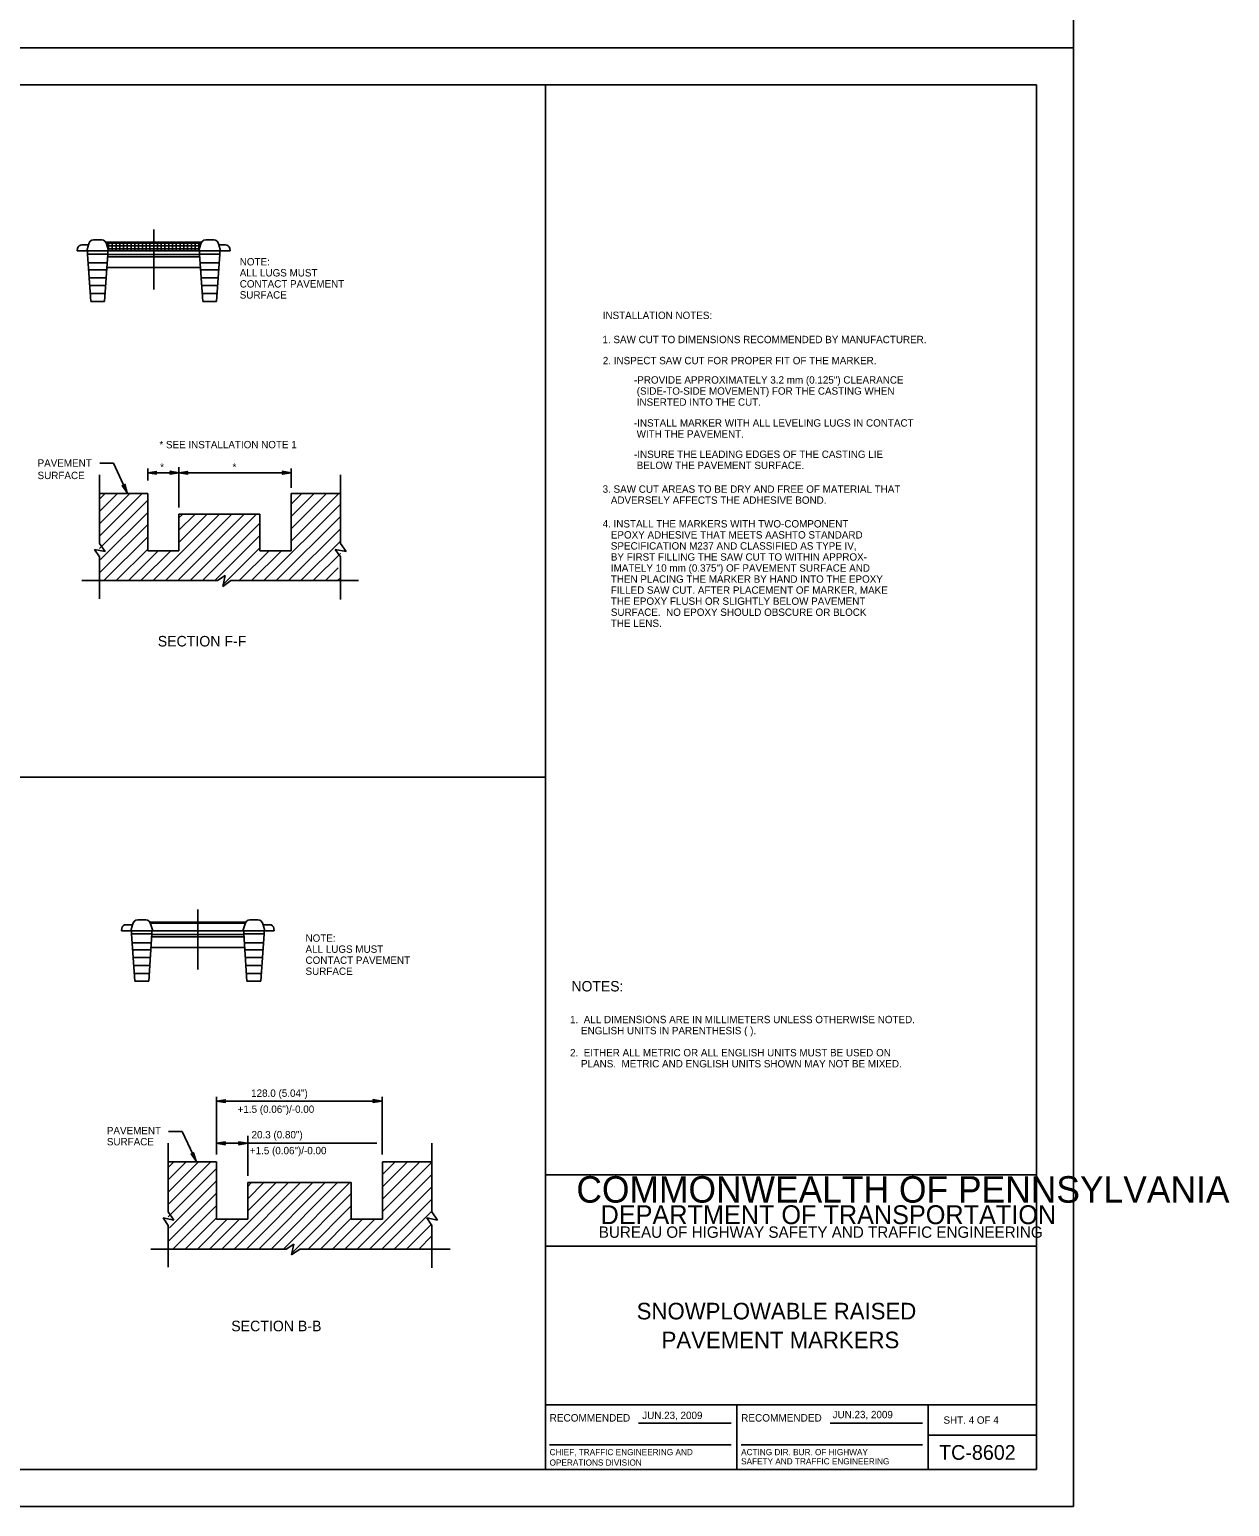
# Model space of a CAD drawing. Extents: x 639362 to 641108, y 298458 to 299646.
# Drawn here: x 640619 to 641108, y 298458 to 299059 of the extents above; entities that cross this region are included whole.
import ezdxf

# ---------------------------------------------------------------- set-up
doc = ezdxf.new("R2010")
doc.units = 0
for name, color, linetype in [('1', 7, 'Continuous'), ('2', 7, 'Continuous'), ('PLT-BNDY', 7, 'Continuous')]:
    doc.layers.add(name, color=color, linetype=linetype)

msp = doc.modelspace()

# ---------------------------------------------------------------- linework, layer by layer
at = {"layer": '1'}
for p, q in [((640243.31, 299036.63), (641029.31, 299036.63)), ((640829.31, 298592.63), (640829.31, 299036.63)), ((641029.31, 298472.63), (641029.31, 299036.63)), ((640243.31, 298754.63), (640829.31, 298754.63)), ((640829.31, 298472.63), (640829.31, 298592.63)), ((640829.31, 298592.63), (641029.31, 298592.63)), ((641029.31, 298563.63), (640829.31, 298563.63)), ((640829.31, 298499), (641029.31, 298499)), ((640907.31, 298499), (640907.31, 298472.63)), ((640985.19, 298472.63), (640985.19, 298499)), ((640867.24, 298491.57), (640904.87, 298491.57)), ((640945.24, 298491.57), (640982.87, 298491.57)), ((640830.99, 298482.68), (640904.87, 298482.68)), ((640908.99, 298482.68), (640982.87, 298482.68)), ((640985.19, 298486.63), (641029.31, 298486.63)), ((641029.31, 298472.63), (640243.31, 298472.63)), ((640243.31, 298472.63), (640829.31, 298472.63))]:
    msp.add_line(p, q, dxfattribs=at)
at = {"layer": '2'}
for p, q in [((640669.77, 298977.68), (640669.77, 298953.22)), ((640638.64, 298969.01), (640638.78, 298969.98)), ((640643.2, 298971.48), (640640.53, 298971.48)), ((640642.5, 298969.01), (640643.19, 298971.43)), ((640645.29, 298973.5), (640648.59, 298973.5)), ((640650.27, 298972.5), (640689.27, 298972.5)), ((640650.48, 298972.11), (640689.08, 298972.11)), ((640651.38, 298969.01), (640650.68, 298971.43)), ((640651.07, 298971.07), (640688.46, 298971.07)), ((640651.07, 298969.88), (640688.46, 298969.88)), ((640651.36, 298972.11), (640651.36, 298969.01)), ((640652.9, 298972.11), (640652.9, 298969.01)), ((640654.43, 298972.11), (640654.43, 298969.01)), ((640655.96, 298972.11), (640655.96, 298969.01)), ((640657.5, 298972.11), (640657.5, 298969.01)), ((640659.03, 298972.11), (640659.03, 298969.01)), ((640660.56, 298972.11), (640660.56, 298969.01)), ((640662.1, 298972.11), (640662.1, 298969.01)), ((640663.63, 298972.11), (640663.63, 298969.01)), ((640665.17, 298972.11), (640665.17, 298969.01)), ((640666.7, 298972.11), (640666.7, 298969.01)), ((640668.23, 298972.11), (640668.23, 298969.01)), ((640669.77, 298972.11), (640669.77, 298969.01)), ((640671.3, 298972.11), (640671.3, 298969.01)), ((640672.83, 298972.11), (640672.83, 298969.01)), ((640674.36, 298972.11), (640674.36, 298969.01)), ((640675.9, 298972.11), (640675.9, 298969.01)), ((640677.43, 298972.11), (640677.43, 298969.01)), ((640678.97, 298972.11), (640678.97, 298969.01)), ((640680.5, 298972.11), (640680.5, 298969.01)), ((640682.03, 298972.11), (640682.03, 298969.01)), ((640683.57, 298972.11), (640683.57, 298969.01)), ((640685.1, 298972.11), (640685.1, 298969.01)), ((640686.63, 298972.11), (640686.63, 298969.01)), ((640688.15, 298969.01), (640688.85, 298971.43)), ((640688.17, 298972.11), (640688.17, 298969.01)), ((640694.24, 298973.5), (640690.94, 298973.5)), ((640696.33, 298971.48), (640699, 298971.48)), ((640697.03, 298969.01), (640696.33, 298971.43)), ((640700.89, 298969.01), (640700.75, 298969.98)), ((640642.75, 298969.01), (640638.64, 298969.01)), ((640642.5, 298969.01), (640651.38, 298969.01)), ((640642.79, 298967.68), (640642.79, 298969.01)), ((640644.12, 298948.4), (640642.79, 298967.68)), ((640642.79, 298967.68), (640651.09, 298967.68)), ((640650.84, 298964.12), (640643.03, 298964.12)), ((640649.77, 298948.4), (640651.09, 298967.68)), ((640651.01, 298966.54), (640688.52, 298966.54)), ((640651.07, 298967.46), (640688.46, 298967.46)), ((640651.09, 298967.68), (640651.09, 298969.01)), ((640651.13, 298969.01), (640688.4, 298969.01)), ((640688.15, 298969.01), (640697.03, 298969.01)), ((640688.44, 298967.68), (640688.44, 298969.01)), ((640689.77, 298948.4), (640688.44, 298967.68)), ((640688.44, 298967.68), (640696.74, 298967.68)), ((640688.68, 298964.12), (640696.5, 298964.12)), ((640695.41, 298948.4), (640696.74, 298967.68)), ((640696.74, 298967.68), (640696.74, 298969.01)), ((640696.78, 298969.01), (640700.89, 298969.01)), ((640650.65, 298961.26), (640643.23, 298961.26)), ((640650.43, 298958.05), (640643.45, 298958.05)), ((640650.71, 298962.2), (640688.82, 298962.2)), ((640688.88, 298961.26), (640696.3, 298961.26)), ((640689.1, 298958.05), (640696.08, 298958.05)), ((640650.21, 298954.83), (640643.68, 298954.83)), ((640649.99, 298951.62), (640643.9, 298951.62)), ((640689.32, 298954.83), (640695.85, 298954.83)), ((640689.54, 298951.62), (640695.63, 298951.62)), ((640649.77, 298948.4), (640644.12, 298948.4)), ((640689.77, 298948.4), (640695.41, 298948.4)), ((640647.82, 298882.56), (640653.38, 298882.56)), ((640653.38, 298882.56), (640659, 298870.44)), ((640667.32, 298880.4), (640667.32, 298875.51)), ((640680.07, 298880.95), (640680.07, 298864.44)), ((640725.71, 298880.4), (640725.71, 298872.49)), ((640647.65, 298877.84), (640647.65, 298849.8)), ((640667.32, 298878.62), (640725.71, 298878.62)), ((640745.78, 298877.84), (640745.78, 298849.8)), ((640667.32, 298870.23), (640647.65, 298870.23)), ((640647.65, 298867.87), (640650.01, 298870.23)), ((640647.65, 298862.86), (640655.02, 298870.23)), ((640647.65, 298857.85), (640660.03, 298870.23)), ((640647.65, 298852.84), (640665.04, 298870.23)), ((640647.65, 298847.83), (640667.32, 298867.5)), ((640667.32, 298870.23), (640667.32, 298846.76)), ((640725.71, 298870.23), (640725.71, 298846.86)), ((640725.71, 298870.23), (640745.78, 298870.23)), ((640725.71, 298865.79), (640730.15, 298870.23)), ((640725.71, 298860.78), (640735.16, 298870.23)), ((640725.71, 298855.77), (640740.17, 298870.23)), ((640725.71, 298850.77), (640745.18, 298870.23)), ((640648.15, 298843.33), (640667.32, 298862.49)), ((640669.56, 298834.68), (640696.61, 298861.73)), ((640674.56, 298834.68), (640701.62, 298861.73)), ((640679.57, 298834.68), (640706.63, 298861.73)), ((640680.07, 298861.73), (640680.07, 298846.86)), ((640712.96, 298861.73), (640680.07, 298861.73)), ((640680.07, 298860.22), (640681.58, 298861.73)), ((640680.07, 298855.21), (640686.59, 298861.73)), ((640680.07, 298850.2), (640691.6, 298861.73)), ((640684.58, 298834.68), (640711.63, 298861.73)), ((640712.96, 298861.73), (640712.96, 298846.76)), ((640714.63, 298834.68), (640745.78, 298865.82)), ((640647.65, 298837.81), (640667.32, 298857.48)), ((640689.59, 298834.68), (640712.96, 298858.05)), ((640719.64, 298834.68), (640745.78, 298860.81)), ((640724.65, 298834.68), (640745.78, 298855.81)), ((640650, 298846.51), (640647.65, 298849.8)), ((640649.52, 298834.68), (640667.32, 298852.47)), ((640694.6, 298834.68), (640712.96, 298853.04)), ((640729.66, 298834.68), (640745.78, 298850.8)), ((640748.13, 298846.51), (640745.78, 298849.8)), ((640647.65, 298844.33), (640645.6, 298847.41)), ((640645.6, 298847.41), (640650, 298846.51)), ((640647.65, 298844.33), (640647.65, 298827.29)), ((640654.53, 298834.68), (640667.32, 298847.47)), ((640659.54, 298834.68), (640671.65, 298846.79)), ((640664.55, 298834.68), (640676.7, 298846.83)), ((640667.32, 298846.86), (640680.07, 298846.86)), ((640698.1, 298833.17), (640712.96, 298848.03)), ((640704.62, 298834.68), (640716.8, 298846.86)), ((640709.62, 298834.68), (640721.8, 298846.86)), ((640712.96, 298846.86), (640725.71, 298846.86)), ((640734.67, 298834.68), (640745.78, 298845.79)), ((640745.78, 298844.33), (640743.73, 298847.41)), ((640743.73, 298847.41), (640748.13, 298846.51)), ((640745.78, 298844.33), (640745.78, 298827.06)), ((640739.68, 298834.68), (640744.9, 298839.89)), ((640695.75, 298834.68), (640640.55, 298834.68)), ((640695.75, 298834.68), (640698.83, 298836.73)), ((640698.83, 298836.73), (640697.93, 298832.33)), ((640697.93, 298832.33), (640701.22, 298834.68)), ((640753.23, 298834.68), (640701.22, 298834.68)), ((640744.68, 298834.68), (640745.78, 298835.77)), ((640687.74, 298700.77), (640687.74, 298676.31)), ((640656.61, 298692.1), (640656.76, 298693.07)), ((640661.18, 298694.57), (640658.51, 298694.57)), ((640660.47, 298692.1), (640661.17, 298694.53)), ((640663.27, 298696.59), (640666.56, 298696.59)), ((640668.24, 298695.6), (640707.24, 298695.6)), ((640668.46, 298695.2), (640707.06, 298695.2)), ((640669.35, 298692.1), (640668.66, 298694.53)), ((640706.13, 298692.1), (640706.82, 298694.53)), ((640712.21, 298696.59), (640708.92, 298696.59)), ((640714.3, 298694.57), (640716.97, 298694.57)), ((640715, 298692.1), (640714.31, 298694.53)), ((640718.87, 298692.1), (640718.72, 298693.07)), ((640660.72, 298692.1), (640656.61, 298692.1)), ((640660.47, 298692.1), (640669.35, 298692.1)), ((640660.76, 298690.78), (640660.76, 298692.1)), ((640662.09, 298671.5), (640660.76, 298690.78)), ((640660.76, 298690.78), (640669.06, 298690.78)), ((640668.82, 298687.21), (640661.01, 298687.21)), ((640667.74, 298671.5), (640669.06, 298690.78)), ((640668.98, 298689.63), (640706.49, 298689.63)), ((640669.05, 298690.55), (640706.43, 298690.55)), ((640669.06, 298690.78), (640669.06, 298692.1)), ((640669.1, 298692.1), (640706.37, 298692.1)), ((640706.13, 298692.1), (640715, 298692.1)), ((640706.41, 298690.78), (640706.41, 298692.1)), ((640707.74, 298671.5), (640706.41, 298690.78)), ((640706.41, 298690.78), (640714.72, 298690.78)), ((640706.66, 298687.21), (640714.47, 298687.21)), ((640713.38, 298671.5), (640714.72, 298690.78)), ((640714.72, 298690.78), (640714.72, 298692.1)), ((640714.76, 298692.1), (640718.87, 298692.1)), ((640668.62, 298684.35), (640661.2, 298684.35)), ((640668.4, 298681.14), (640661.43, 298681.14)), ((640668.69, 298685.3), (640706.79, 298685.3)), ((640706.85, 298684.35), (640714.27, 298684.35)), ((640707.08, 298681.14), (640714.05, 298681.14)), ((640668.18, 298677.93), (640661.65, 298677.93)), ((640707.3, 298677.93), (640713.83, 298677.93)), ((640667.96, 298674.71), (640661.87, 298674.71)), ((640667.74, 298671.5), (640662.09, 298671.5)), ((640707.52, 298674.71), (640713.6, 298674.71)), ((640707.74, 298671.5), (640713.38, 298671.5)), ((640695.32, 298624.5), (640695.32, 298601)), ((640695.32, 298622.72), (640762.65, 298622.72)), ((640762.82, 298624.5), (640762.82, 298601)), ((640675.82, 298610.34), (640681.38, 298610.34)), ((640681.38, 298610.34), (640687.01, 298598.21)), ((640675.65, 298605.61), (640675.65, 298577.57)), ((640695.32, 298605.54), (640760.58, 298605.54)), ((640708.07, 298608.54), (640708.07, 298592.22)), ((640783.03, 298605.61), (640783.03, 298577.57)), ((640695.32, 298598), (640675.65, 298598)), ((640675.65, 298595.64), (640678.02, 298598)), ((640675.65, 298590.63), (640683.03, 298598)), ((640675.65, 298585.62), (640688.04, 298598)), ((640675.65, 298580.61), (640693.04, 298598)), ((640695.32, 298598), (640695.32, 298574.53)), ((640762.96, 298598), (640762.96, 298574.63)), ((640762.96, 298598), (640783.03, 298598)), ((640762.96, 298582.78), (640778.19, 298598)), ((640762.96, 298587.78), (640773.18, 298598)), ((640762.96, 298592.79), (640768.17, 298598)), ((640762.96, 298577.77), (640783.03, 298597.84)), ((640675.65, 298575.6), (640695.32, 298595.27)), ((640752.65, 298562.45), (640783.03, 298592.83)), ((640675.65, 298565.59), (640695.32, 298585.26)), ((640676.16, 298571.1), (640695.32, 298590.27)), ((640697.56, 298562.45), (640724.61, 298589.5)), ((640702.57, 298562.45), (640729.62, 298589.5)), ((640707.58, 298562.45), (640734.63, 298589.5)), ((640708.07, 298589.5), (640708.07, 298574.63)), ((640750.21, 298589.5), (640708.07, 298589.5)), ((640708.07, 298587.99), (640709.59, 298589.5)), ((640708.07, 298582.98), (640714.6, 298589.5)), ((640708.07, 298577.97), (640719.6, 298589.5)), ((640712.59, 298562.45), (640739.64, 298589.5)), ((640717.59, 298562.45), (640744.65, 298589.5)), ((640722.6, 298562.45), (640749.66, 298589.5)), ((640726.11, 298560.95), (640750.21, 298585.05)), ((640750.21, 298589.5), (640750.21, 298574.53)), ((640757.66, 298562.45), (640783.03, 298587.82)), ((640677.53, 298562.45), (640695.32, 298580.25)), ((640732.62, 298562.45), (640750.21, 298580.04)), ((640762.67, 298562.45), (640783.03, 298582.81)), ((640675.65, 298572.11), (640673.6, 298575.19)), ((640673.6, 298575.19), (640678, 298574.28)), ((640678, 298574.28), (640675.65, 298577.57)), ((640682.53, 298562.45), (640695.32, 298575.24)), ((640687.54, 298562.45), (640699.66, 298574.57)), ((640692.55, 298562.45), (640704.7, 298574.6)), ((640695.32, 298574.63), (640708.07, 298574.63)), ((640737.63, 298562.45), (640750.21, 298575.03)), ((640742.64, 298562.45), (640754.82, 298574.63)), ((640747.64, 298562.45), (640759.82, 298574.63)), ((640750.21, 298574.63), (640762.96, 298574.63)), ((640767.68, 298562.45), (640782.93, 298577.71)), ((640783.03, 298572.11), (640780.98, 298575.19)), ((640780.98, 298575.19), (640785.38, 298574.28)), ((640785.38, 298574.28), (640783.03, 298577.57)), ((640675.65, 298572.11), (640675.65, 298555.07)), ((640772.69, 298562.45), (640782.75, 298572.52)), ((640777.7, 298562.45), (640783.03, 298567.78)), ((640783.03, 298572.11), (640783.03, 298554.84)), ((640723.76, 298562.45), (640668.55, 298562.45)), ((640723.76, 298562.45), (640726.84, 298564.5)), ((640726.84, 298564.5), (640725.93, 298560.1)), ((640725.93, 298560.1), (640729.22, 298562.45)), ((640790.48, 298562.45), (640729.22, 298562.45))]:
    msp.add_line(p, q, dxfattribs=at)
for points in [[(640657.96, 298873.71), (640657.79, 298873.49), (640659, 298870.44), (640657.96, 298873.71), (640658.02, 298873.93), (640659, 298870.44), (640657.48, 298873.34), (640657.21, 298873.35), (640659, 298870.44), (640656.98, 298873.45), (640657.21, 298873.35)], [(640670.72, 298878.2), (640670.6, 298878.44), (640667.32, 298878.62), (640670.72, 298878.2), (640670.9, 298878.05), (640667.32, 298878.62), (640670.59, 298878.79), (640670.71, 298879.03), (640667.32, 298878.62), (640670.9, 298879.19), (640670.71, 298879.03)], [(640676.59, 298879.05), (640676.71, 298878.8), (640679.99, 298878.62), (640676.59, 298879.05), (640676.42, 298879.2), (640679.99, 298878.62), (640676.72, 298878.46), (640676.6, 298878.22), (640679.99, 298878.62), (640676.42, 298878.05), (640676.6, 298878.22)], [(640683.47, 298878.2), (640683.35, 298878.44), (640680.07, 298878.62), (640683.47, 298878.2), (640683.65, 298878.04), (640680.07, 298878.62), (640683.34, 298878.79), (640683.46, 298879.03), (640680.07, 298878.62), (640683.65, 298879.19), (640683.46, 298879.03)], [(640722.31, 298879.05), (640722.43, 298878.8), (640725.71, 298878.62), (640722.31, 298879.05), (640722.13, 298879.2), (640725.71, 298878.62), (640722.44, 298878.46), (640722.32, 298878.22), (640725.71, 298878.62), (640722.13, 298878.05), (640722.32, 298878.22)], [(640698.73, 298622.3), (640698.6, 298622.54), (640695.32, 298622.72), (640698.73, 298622.3), (640698.9, 298622.15), (640695.32, 298622.72), (640698.6, 298622.89), (640698.72, 298623.13), (640695.32, 298622.72), (640698.9, 298623.29), (640698.72, 298623.13)], [(640759.25, 298623.15), (640759.38, 298622.9), (640762.65, 298622.72), (640759.25, 298623.15), (640759.08, 298623.3), (640762.65, 298622.72), (640759.38, 298622.56), (640759.26, 298622.32), (640762.65, 298622.72), (640759.08, 298622.15), (640759.26, 298622.32)], [(640698.73, 298605.11), (640698.6, 298605.36), (640695.32, 298605.54), (640698.73, 298605.11), (640698.9, 298604.96), (640695.32, 298605.54), (640698.6, 298605.7), (640698.72, 298605.94), (640695.32, 298605.54), (640698.9, 298606.11), (640698.72, 298605.94)], [(640704.59, 298605.96), (640704.72, 298605.72), (640708, 298605.53), (640704.59, 298605.96), (640704.42, 298606.11), (640708, 298605.53), (640704.73, 298605.37), (640704.6, 298605.13), (640708, 298605.53), (640704.42, 298604.97), (640704.6, 298605.13)], [(640685.96, 298601.48), (640685.79, 298601.26), (640687.01, 298598.21), (640685.96, 298601.48), (640686.03, 298601.7), (640687.01, 298598.21), (640685.48, 298601.12), (640685.21, 298601.12), (640687.01, 298598.21), (640684.99, 298601.22), (640685.21, 298601.12)]]:
    msp.add_lwpolyline(points, dxfattribs=at)
for centre, start, end in [((640640.53, 298969.71), 90, 171.21944), ((640698.99, 298969.71), 8.78056, 90), ((640658.51, 298692.8), 90, 171.21944), ((640716.97, 298692.8), 8.78056, 90)]:
    msp.add_arc(centre, 1.77, start, end, dxfattribs=at)
for centre, start_param, end_param in [((640645.29, 298970.84), 0, 1.34621), ((640648.58, 298970.84), 4.937133, 6.283185), ((640690.94, 298970.84), 0, 1.346052), ((640694.24, 298970.84), 4.936975, 6.283185), ((640663.27, 298693.94), 0, 1.34621), ((640666.56, 298693.94), 4.937133, 6.283185), ((640708.92, 298693.94), 0, 1.346052), ((640712.21, 298693.94), 4.936975, 6.283185)]:
    msp.add_ellipse(centre, major_axis=(0, 2.66), ratio=0.81, start_param=start_param, end_param=end_param, dxfattribs=at)
at = {"layer": 'PLT-BNDY'}
for points in [[(640203.31, 299645.63), (641044.31, 299645.63), (641044.31, 299051.63), (640203.31, 299051.63)], [(640203.31, 299051.63), (641044.31, 299051.63), (641044.31, 298457.63), (640203.31, 298457.63)]]:
    msp.add_lwpolyline(points, close=True, dxfattribs=at)

# ---------------------------------------------------------------- texts
at = {"layer": '1'}
for s, height, p in [('COMMONWEALTH OF PENNSYLVANIA', 10.7828, (640841.9, 298581.36)), ('DEPARTMENT OF TRANSPORTATION', 7.6837, (640851.76, 298572.61)), ('BUREAU OF HIGHWAY SAFETY AND TRAFFIC ENGINEERING', 4.6253, (640851.04, 298567.04)), ('SNOWPLOWABLE RAISED', 6.75, (640866.46, 298533.81)), ('PAVEMENT MARKERS', 6.75, (640876.61, 298522.06)), ('RECOMMENDED', 3.048, (640830.99, 298492.2)), ('RECOMMENDED', 3.048, (640908.99, 298492.2)), ('SHT. 4 OF 4', 3, (640991.4, 298491.31)), ('TC-8602', 6, (640989.6, 298476.63)), ('OPERATIONS DIVISION', 2.5, (640830.99, 298474.26)), ('CHIEF, TRAFFIC ENGINEERING AND', 2.5, (640830.99, 298478.51)), ('ACTING DIR. BUR. OF HIGHWAY', 2.5, (640908.99, 298478.51)), ('SAFETY AND TRAFFIC ENGINEERING', 2.5, (640908.99, 298474.76))]:
    msp.add_text(s, height=height, dxfattribs=at).set_placement(p)
for p in [(640868.72, 298493.23), (640946.25, 298493.56)]:
    msp.add_text('JUN.23, 2009', height=3, rotation=360, dxfattribs=at).set_placement(p)
at = {"layer": '2'}
for s, height, p in [('NOTE:', 3, (640704.81, 298963.06)), ('ALL LUGS MUST ', 3.0001, (640704.81, 298958.56)), ('SURFACE', 3, (640704.81, 298949.56)), ('CONTACT PAVEMENT', 3.0001, (640704.81, 298954.06)), ('INSTALLATION NOTES:', 3, (640852.62, 298941.23)), ('1. SAW CUT TO DIMENSIONS RECOMMENDED BY MANUFACTURER.', 3, (640852.53, 298931.39)), ('2. INSPECT SAW CUT FOR PROPER FIT OF THE MARKER.', 3, (640852.67, 298922.81)), ('-PROVIDE APPROXIMATELY 3.2 mm (0.125") CLEARANCE', 3, (640865.37, 298914.92)), (' (SIDE-TO-SIDE MOVEMENT) FOR THE CASTING WHEN', 3, (640865.37, 298910.42)), (' INSERTED INTO THE CUT.', 3, (640865.37, 298905.92)), ('-INSTALL MARKER WITH ALL LEVELING LUGS IN CONTACT', 3, (640865.33, 298897.41)), ('* SEE INSTALLATION NOTE 1', 3, (640672.08, 298888.58)), (' WITH THE PAVEMENT.', 3, (640865.33, 298892.91)), ('-INSURE THE LEADING EDGES OF THE CASTING LIE ', 3, (640865.37, 298884.65)), ('PAVEMENT', 3, (640622.48, 298881.09)), ('*', 3, (640672.42, 298879.45)), ('*', 3, (640701.87, 298879.45)), (' BELOW THE PAVEMENT SURFACE.', 3, (640865.37, 298880.15)), ('SURFACE', 3, (640622.48, 298876.03)), ('3. SAW CUT AREAS TO BE DRY AND FREE OF MATERIAL THAT', 3, (640852.59, 298870.47)), ('   ADVERSELY AFFECTS THE ADHESIVE BOND.', 3, (640852.59, 298865.97)), ('4. INSTALL THE MARKERS WITH TWO-COMPONENT', 3, (640852.59, 298856.33)), ('   SPECIFICATION M237 AND CLASSIFIED AS TYPE IV,', 3, (640852.59, 298847.33)), ('   EPOXY ADHESIVE THAT MEETS AASHTO STANDARD', 3, (640852.59, 298851.83)), ('   BY FIRST FILLING THE SAW CUT TO WITHIN APPROX-', 3, (640852.59, 298842.83)), ('   IMATELY 10 mm (0.375") OF PAVEMENT SURFACE AND', 3, (640852.59, 298838.33)), ('   THEN PLACING THE MARKER BY HAND INTO THE EPOXY', 3, (640852.59, 298833.83)), ('   FILLED SAW CUT. AFTER PLACEMENT OF MARKER, MAKE', 3, (640852.59, 298829.33)), ('   THE EPOXY FLUSH OR SLIGHTLY BELOW PAVEMENT', 3, (640852.59, 298824.83)), ('   SURFACE.  NO EPOXY SHOULD OBSCURE OR BLOCK', 3, (640852.59, 298820.33)), ('   THE LENS.', 3, (640852.59, 298815.83)), ('SECTION F-F', 4.3, (640671.41, 298807.87)), ('NOTE:', 3, (640731.6, 298687.61)), ('ALL LUGS MUST ', 3.0001, (640731.6, 298683.11)), ('CONTACT PAVEMENT', 3.0001, (640731.6, 298678.61)), ('SURFACE', 3, (640731.6, 298674.11)), ('NOTES:', 4.25, (640839.9, 298667.37)), ('1.  ALL DIMENSIONS ARE IN MILLIMETERS UNLESS OTHERWISE NOTED.', 3, (640839.33, 298654.44)), ('    ENGLISH UNITS IN PARENTHESIS ( ).', 3, (640839.33, 298649.94)), ('2.  EITHER ALL METRIC OR ALL ENGLISH UNITS MUST BE USED ON', 3, (640839.33, 298640.94)), ('    PLANS.  METRIC AND ENGLISH UNITS SHOWN MAY NOT BE MIXED.', 3, (640839.33, 298636.44)), ('128.0 (5.04")', 3, (640709.45, 298624.45)), ('+1.5 (0.06")/-0.00', 3, (640703.95, 298617.92)), ('PAVEMENT', 3, (640650.69, 298609.19)), ('20.3 (0.80")', 3, (640709.62, 298607.53)), ('SURFACE', 3, (640650.69, 298604.69)), ('+1.5 (0.06")/-0.00', 3, (640708.93, 298601.07)), ('SECTION B-B', 4.3, (640701.35, 298528.98))]:
    msp.add_text(s, height=height, dxfattribs=at).set_placement(p)

doc.saveas('drawing.dxf')
